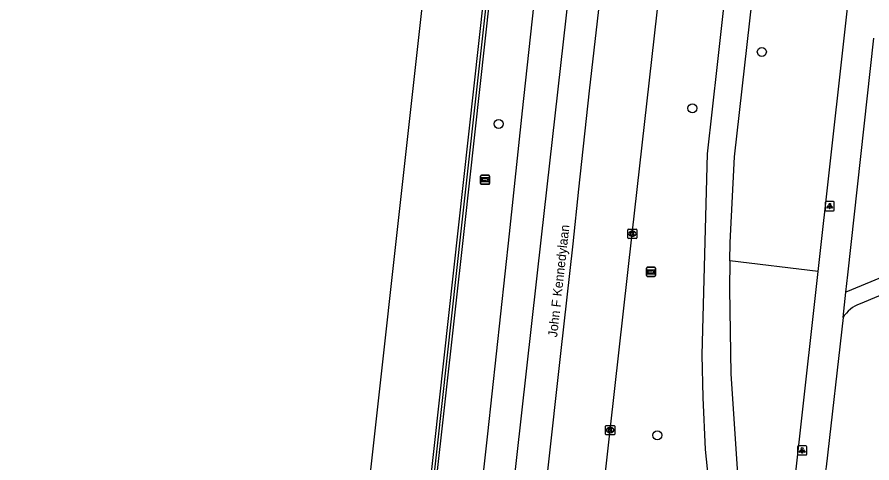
# Model space of a CAD drawing. Extents: x 162026 to 163499, y 387297 to 388169.
# Drawn here: x 162038 to 162130.7, y 387862 to 387910.4 of the extents above; entities that cross this region are included whole.
import ezdxf

# ---------------------------------------------------------------- set-up
doc = ezdxf.new("R2010")
doc.units = 0
for name, color, linetype in [('IMGEO_Berm_groen', 7, 'Continuous'), ('IMGEO_Boom', 7, 'Continuous'), ('IMGEO_Fietspad_gesloten', 7, 'Continuous'), ('IMGEO_Haag', 7, 'Continuous'), ('IMGEO_Hek', 7, 'Continuous'), ('IMGEO_Kolk', 7, 'Continuous'), ('IMGEO_Lichtpunt', 7, 'Continuous'), ('IMGEO_Openbare_ruimte_label', 7, 'Continuous'), ('IMGEO_Rijbaan_regionaal_gesloten', 7, 'Continuous'), ('IMGEO_Voetpad_open', 7, 'Continuous'), ('IMGEO_Wegwijzer', 7, 'Continuous')]:
    doc.layers.add(name, color=color, linetype=linetype)

msp = doc.modelspace()

# ---------------------------------------------------------------- linework, layer by layer
at = {"layer": 'IMGEO_Berm_groen'}
msp.add_lwpolyline([(162124.863, 387882.786), (162115.302, 387883.943)], dxfattribs=at)
at = {"layer": 'IMGEO_Boom'}
for centre in [(162118.763, 387906.602), (162111.241, 387900.48), (162090.229, 387898.791), (162107.444, 387864.994)]:
    msp.add_circle(centre, 0.489, dxfattribs=at)
at = {"layer": 'IMGEO_Fietspad_gesloten'}
for points in [[(162113.437, 387855.753), (162112.662, 387863.447), (162112.42, 387869.087), (162112.294, 387873.71), (162112.881, 387895.541), (162113.946, 387905.236), (162124.476, 388000), (162125.11, 388005.69)], [(162115.302, 387883.943), (162115.329, 387885.915), (162115.802, 387895.208), (162118.544, 387919.647)], [(162115.302, 387883.943), (162115.26, 387880.834), (162115.389, 387871.674), (162116.414, 387856.479), (162117.252, 387848.685)]]:
    msp.add_lwpolyline(points, dxfattribs=at)
at = {"layer": 'IMGEO_Haag'}
msp.add_lwpolyline([(162070.558, 387750.033), (162070.715, 387751.433), (162082.73, 387858.959), (162085.888, 387887.498), (162092.582, 387948.213), (162098.331, 388000.033), (162100.436, 388019.009), (162101.034, 388018.962), (162098.927, 387999.967), (162093.178, 387948.147), (162086.483, 387887.426), (162083.326, 387858.893), (162071.311, 387751.367), (162071.154, 387749.967), (162064.775, 387692.973), (162048.017, 387543.217), (162038.634, 387465.803), (162038.336, 387465.839), (162038.038, 387465.875), (162047.421, 387543.289), (162064.177, 387693.016), (162070.558, 387750.033)], dxfattribs=at)
at = {"layer": 'IMGEO_Hek'}
for points in [[(162112.343, 388167.962), (162112.333, 388167.506), (162111.999, 388154.871), (162111.544, 388142.241), (162110.97, 388129.615), (162110.276, 388116.995), (162109.462, 388104.382), (162108.529, 388091.778), (162107.705, 388081.806), (162098.629, 388000), (162092.88, 387948.18), (162086.186, 387887.462)], [(162086.186, 387887.462), (162083.028, 387858.926), (162071.013, 387751.4), (162070.856, 387750), (162064.476, 387692.994)]]:
    msp.add_lwpolyline(points, dxfattribs=at)
at = {"layer": 'IMGEO_Kolk'}
for p, q in [((162104.222, 387886.44), (162104.222, 387887.292)), ((162104.297, 387887.366), (162105.149, 387887.366)), ((162105.223, 387887.292), (162105.223, 387886.44)), ((162105.149, 387886.366), (162104.297, 387886.366)), ((162104.733, 387886.586), (162104.708, 387886.586)), ((162104.71, 387887.146), (162104.735, 387887.146)), ((162101.818, 387865.125), (162101.818, 387865.977)), ((162101.893, 387866.051), (162102.745, 387866.051)), ((162102.819, 387865.977), (162102.819, 387865.125)), ((162102.745, 387865.051), (162101.893, 387865.051)), ((162102.329, 387865.271), (162102.304, 387865.271)), ((162102.306, 387865.831), (162102.331, 387865.831))]:
    msp.add_line(p, q, dxfattribs=at)
for points in [[(162104.222, 387886.44), (162104.222, 387887.292)], [(162104.297, 387887.366), (162105.149, 387887.366)], [(162105.223, 387887.292), (162105.223, 387886.44)], [(162105.149, 387886.366), (162104.297, 387886.366)], [(162104.543, 387887.066), (162104.666, 387887.066), (162104.666, 387886.915), (162104.796, 387887.066), (162104.96, 387887.066), (162104.814, 387886.915), (162104.967, 387886.666), (162104.815, 387886.666), (162104.73, 387886.83), (162104.666, 387886.763), (162104.666, 387886.666), (162104.543, 387886.666), (162104.543, 387887.066)], [(162101.818, 387865.125), (162101.818, 387865.977)], [(162101.893, 387866.051), (162102.745, 387866.051)], [(162102.819, 387865.977), (162102.819, 387865.125)], [(162102.745, 387865.051), (162101.893, 387865.051)], [(162102.139, 387865.751), (162102.262, 387865.751), (162102.262, 387865.6), (162102.392, 387865.751), (162102.556, 387865.751), (162102.41, 387865.6), (162102.563, 387865.351), (162102.411, 387865.351), (162102.326, 387865.515), (162102.262, 387865.448), (162102.262, 387865.351), (162102.139, 387865.351), (162102.139, 387865.751)]]:
    msp.add_lwpolyline(points, dxfattribs=at)
for centre, start, end in [((162104.299, 387887.29), 91.55205, 178.44795), ((162104.299, 387887.29), 91.55205, 178.44795), ((162105.147, 387887.29), 1.55205, 88.44795), ((162105.147, 387887.29), 1.55205, 88.44795), ((162104.299, 387886.442), 181.55205, 268.44795), ((162104.299, 387886.442), 181.55205, 268.44795), ((162105.147, 387886.442), 271.55205, 358.44795), ((162105.147, 387886.442), 271.55205, 358.44795), ((162101.895, 387865.975), 91.55205, 178.44795), ((162101.895, 387865.975), 91.55205, 178.44795), ((162102.743, 387865.975), 1.55205, 88.44795), ((162102.743, 387865.975), 1.55205, 88.44795), ((162101.895, 387865.127), 181.55205, 268.44795), ((162101.895, 387865.127), 181.55205, 268.44795), ((162102.743, 387865.127), 271.55205, 358.44795), ((162102.743, 387865.127), 271.55205, 358.44795)]:
    msp.add_arc(centre, 0.0765, start, end, dxfattribs=at)
for centre, major_axis, ratio, start_param, end_param in [((162104.709, 387886.866), (-0.387, 0.002), 0.722429, 4.712389, 7.853982), ((162104.734, 387886.866), (-0.39, 0.002), 0.717154, 1.570796, 4.712389), ((162102.305, 387865.551), (-0.387, 0.002), 0.722429, 4.712389, 7.853982), ((162102.33, 387865.551), (-0.39, 0.002), 0.717154, 1.570796, 4.712389)]:
    msp.add_ellipse(centre, major_axis=major_axis, ratio=ratio, start_param=start_param, end_param=end_param, dxfattribs=at)
at = {"layer": 'IMGEO_Lichtpunt'}
for p, q in [((162125.621, 387890.264), (162125.621, 387889.457)), ((162125.621, 387890.264), (162125.621, 387889.457)), ((162126.523, 387890.359), (162125.715, 387890.359)), ((162126.523, 387890.359), (162125.715, 387890.359)), ((162126.617, 387889.457), (162126.617, 387890.264)), ((162126.617, 387889.457), (162126.617, 387890.264)), ((162125.715, 387889.363), (162126.523, 387889.363)), ((162125.715, 387889.363), (162126.523, 387889.363)), ((162122.637, 387863.755), (162122.637, 387862.948)), ((162122.637, 387863.755), (162122.637, 387862.948)), ((162123.539, 387863.85), (162122.731, 387863.85)), ((162123.539, 387863.85), (162122.731, 387863.85)), ((162123.633, 387862.948), (162123.633, 387863.755)), ((162123.633, 387862.948), (162123.633, 387863.755)), ((162122.731, 387862.854), (162123.539, 387862.854)), ((162122.731, 387862.854), (162123.539, 387862.854))]:
    msp.add_line(p, q, dxfattribs=at)
for points in [[(162125.995, 387889.928), (162126.034, 387889.9), (162125.846, 387889.638), (162125.808, 387889.665), (162125.995, 387889.928)], [(162126.097, 387889.88), (162126.144, 387889.88), (162126.144, 387889.558), (162126.097, 387889.558), (162126.097, 387889.88)], [(162126.207, 387889.9), (162126.245, 387889.927), (162126.432, 387889.665), (162126.393, 387889.637), (162126.207, 387889.9)], [(162123.011, 387863.419), (162123.05, 387863.391), (162122.862, 387863.129), (162122.824, 387863.156), (162123.011, 387863.419)], [(162123.113, 387863.371), (162123.16, 387863.371), (162123.16, 387863.049), (162123.113, 387863.049), (162123.113, 387863.371)], [(162123.223, 387863.391), (162123.261, 387863.418), (162123.448, 387863.156), (162123.409, 387863.128), (162123.223, 387863.391)]]:
    msp.add_lwpolyline(points, dxfattribs=at)
for centre in [(162126.12, 387890.062), (162123.136, 387863.553)]:
    msp.add_circle(centre, 0.0994, dxfattribs=at)
for centre, start, end in [((162125.715, 387890.264), 90, 180), ((162125.715, 387890.264), 90, 180), ((162126.523, 387890.264), 0, 90), ((162126.523, 387890.264), 0, 90), ((162125.715, 387889.457), 180, 270), ((162125.715, 387889.457), 180, 270), ((162126.523, 387889.457), 270, 0), ((162126.523, 387889.457), 270, 360), ((162122.731, 387863.755), 90, 180), ((162122.731, 387863.755), 90, 180), ((162123.539, 387863.755), 0, 90), ((162123.539, 387863.755), 0, 90), ((162122.731, 387862.948), 180, 270), ((162122.731, 387862.948), 180, 270), ((162123.539, 387862.948), 270, 0), ((162123.539, 387862.948), 270, 360)]:
    msp.add_arc(centre, 0.0946, start, end, dxfattribs=at)
at = {"layer": 'IMGEO_Rijbaan_regionaal_gesloten'}
for points in [[(162056.727, 387684.126), (162057.767, 387693.483), (162064.05, 387750), (162079.391, 387888.288), (162091.784, 388000), (162095.156, 388030.116), (162098.969, 388066.214), (162102.065, 388098.695), (162105.018, 388137.039), (162105.974, 388153.499), (162106.66, 388168.525), (162106.66, 388168.525)], [(162115.185, 388167.681), (162115.185, 388167.681), (162115.08, 388160.108), (162114.774, 388146.796), (162113.246, 388115.179), (162111.257, 388082.374), (162107.741, 388040.671), (162103.786, 388000), (162102.643, 387988.4), (162096.151, 387931.204), (162092.788, 387900.224), (162091.359, 387886.839), (162089.042, 387865.143), (162076.229, 387750), (162071.42, 387707.267), (162069.77, 387692.609), (162059.518, 387601.502), (162048.26, 387500), (162043.118, 387453.488)], [(162118.847, 388167.319), (162118.784, 388163.821), (162118.414, 388149.01), (162117.683, 388128.448), (162116.859, 388112.665), (162115.926, 388096.828), (162114.902, 388081.118), (162113.723, 388065.297), (162112.335, 388048.541), (162109.282, 388016.74), (162106.505, 387990.085), (162103.819, 387966.184), (162094.856, 387886.497), (162087.297, 387818.939), (162079.611, 387750.509), (162073.014, 387691.729), (162068.986, 387656.002), (162065.336, 387623.382), (162060.869, 387583.595), (162055.598, 387536.533), (162051.705, 387501.521), (162046.313, 387453.259)], [(162113.732, 388027.667), (162112.333, 388013.732), (162111.302, 388003.77), (162110.16, 387992.987), (162108.956, 387981.989), (162108.052, 387973.989), (162106.738, 387962.076), (162105.165, 387948.106), (162104.337, 387940.147), (162103.663, 387934.281), (162102.325, 387922.313), (162101.435, 387914.378), (162100.058, 387902.373), (162098.894, 387891.718), (162098.265, 387885.779), (162096.931, 387873.862), (162095.488, 387860.805), (162094.387, 387850.878), (162093.057, 387838.959), (162091.504, 387825.016), (162089.98, 387811.145), (162088.603, 387799.212), (162087.295, 387787.326)], [(162101.414, 387857.699), (162101.619, 387859.357), (162102.319, 387865.551), (162104.723, 387886.866), (162107.676, 387913.177), (162110.033, 387934.503), (162110.908, 387942.663)]]:
    msp.add_lwpolyline(points, dxfattribs=at)
at = {"layer": 'IMGEO_Voetpad_open'}
for points in [[(162124.863, 387882.786), (162128.829, 387918.498)], [(162127.867, 387880.534), (162128.072, 387882.398), (162130.895, 387908.088)], [(162146.955, 387888.433), (162143.344, 387886.938), (162127.867, 387880.534)], [(162146.176, 387886.28), (162129.409, 387879.271)], [(162120.863, 387846.697), (162124.863, 387882.786)], [(162127.562, 387877.764), (162127.867, 387880.534)], [(162127.562, 387877.764), (162125.733, 387861.584), (162125.681, 387861.129)]]:
    msp.add_lwpolyline(points, dxfattribs=at)
msp.add_arc((162130.684, 387875.823), 3.676, 110.29284, 148.13039, dxfattribs=at)
at = {"layer": 'IMGEO_Wegwijzer'}
for p, q in [((162088.27, 387892.333), (162088.27, 387893.133)), ((162088.27, 387893.133), (162088.27, 387892.333)), ((162088.37, 387893.233), (162089.16, 387893.233)), ((162089.16, 387893.233), (162088.37, 387893.233)), ((162089.26, 387893.133), (162089.26, 387892.333)), ((162089.26, 387892.333), (162089.26, 387893.133)), ((162089.16, 387892.233), (162088.37, 387892.233)), ((162088.37, 387892.233), (162089.16, 387892.233)), ((162106.251, 387882.323), (162106.251, 387883.123)), ((162106.251, 387883.123), (162106.251, 387882.323)), ((162106.351, 387883.223), (162107.141, 387883.223)), ((162107.141, 387883.223), (162106.351, 387883.223)), ((162107.241, 387883.123), (162107.241, 387882.323)), ((162107.241, 387882.323), (162107.241, 387883.123)), ((162107.141, 387882.223), (162106.351, 387882.223)), ((162106.351, 387882.223), (162107.141, 387882.223))]:
    msp.add_line(p, q, dxfattribs=at)
for points in [[(162088.371, 387892.965), (162089.159, 387892.965), (162089.159, 387892.501), (162088.371, 387892.501), (162088.371, 387892.965)], [(162088.436, 387892.817), (162088.436, 387892.733), (162088.436, 387892.649), (162088.847, 387892.649), (162088.847, 387892.566), (162089.094, 387892.733), (162088.847, 387892.9), (162088.847, 387892.817), (162088.436, 387892.817)], [(162106.352, 387882.955), (162107.14, 387882.955), (162107.14, 387882.491), (162106.352, 387882.491), (162106.352, 387882.955)], [(162106.417, 387882.807), (162106.417, 387882.723), (162106.417, 387882.639), (162106.828, 387882.639), (162106.828, 387882.556), (162107.075, 387882.723), (162106.828, 387882.89), (162106.828, 387882.807), (162106.417, 387882.807)]]:
    msp.add_lwpolyline(points, dxfattribs=at)
for centre, start, end in [((162088.37, 387893.133), 90, 180), ((162088.37, 387893.133), 90, 180), ((162089.16, 387893.133), 0, 90), ((162089.16, 387893.133), 360, 90), ((162088.37, 387892.333), 180, 270), ((162088.37, 387892.333), 180, 270), ((162089.16, 387892.333), 270, 0), ((162089.16, 387892.333), 270, 0), ((162106.351, 387883.123), 90, 180), ((162106.351, 387883.123), 90, 180), ((162107.141, 387883.123), 0, 90), ((162107.141, 387883.123), 360, 90), ((162106.351, 387882.323), 180, 270), ((162106.351, 387882.323), 180, 270), ((162107.141, 387882.323), 270, 0), ((162107.141, 387882.323), 270, 0)]:
    msp.add_arc(centre, 0.1, start, end, dxfattribs=at)

# ---------------------------------------------------------------- texts
at = {"layer": 'IMGEO_Openbare_ruimte_label'}
msp.add_text('John F Kennedylaan', height=1, rotation=83.68512, dxfattribs=at).set_placement((162096.57, 387875.595))

doc.saveas('drawing.dxf')
